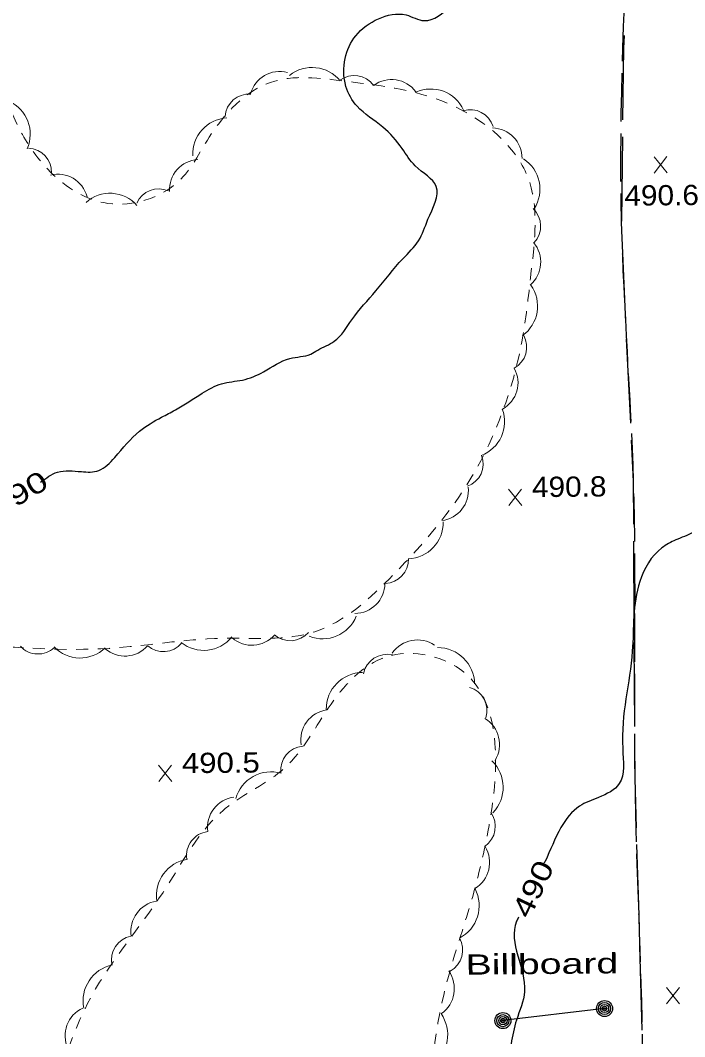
# Model space of a CAD drawing. Extents: x 2362213 to 2366494, y 6968794 to 6978110.
# Drawn here: x 2364075.5 to 2364233.1, y 6971102 to 6971343.1 of the extents above; entities that cross this region are included whole.
import ezdxf
from ezdxf.enums import TextEntityAlignment as Align

# ---------------------------------------------------------------- set-up
doc = ezdxf.new("R2010")
doc.units = 0
doc.header["$LTSCALE"] = 1.9
for name, pattern in [('DASH_DOUBLE_DOT', [9.2, 5, -1.2, 0.3, -1.2, 0.3, -1.2]), ('LONG_DASHED', [7.5, 6, -1.5]), ('SHORT_DASHED', [2.7, 1.5, -1.2])]:
    doc.linetypes.add(name, pattern=pattern)
for name, color, linetype, lineweight in [('21', 7, 'Continuous', 25), ('25', 7, 'Continuous', 25), ('29', 7, 'Continuous', 13), ('3', 7, 'Continuous', 25), ('31', 7, 'Continuous', 25)]:
    doc.layers.add(name, color=color, linetype=linetype, lineweight=lineweight)

msp = doc.modelspace()

# ---------------------------------------------------------------- linework, layer by layer
at = {"layer": '21'}
msp.add_line((2364214.103, 6971108.656), (2364189.99, 6971105.785), dxfattribs=at)
for centre, radius in [((2364214.103, 6971108.656), 1.9), ((2364214.103, 6971108.656), 1.442), ((2364214.103, 6971108.656), 0.973), ((2364189.989, 6971105.786), 1.9), ((2364189.989, 6971105.786), 1.442), ((2364214.103, 6971108.656), 0.539), ((2364214.103, 6971108.656), 0.192), ((2364189.989, 6971105.786), 0.973), ((2364189.989, 6971105.786), 0.539), ((2364189.989, 6971105.786), 0.192)]:
    msp.add_circle(centre, radius, dxfattribs=at)
at = {"layer": '25', "linetype": 'DASH_DOUBLE_DOT'}
msp.add_spline([(2363816.795, 6971226.248), (2363836.192, 6971228.743), (2363863.6, 6971232.244), (2363891.907, 6971241.034), (2363911.32, 6971252.379), (2363929.963, 6971264.788), (2363940.409, 6971286.278), (2363942.727, 6971325.332), (2363941.383, 6971367.741), (2363938.463, 6971413.955), (2363937.543, 6971444.378), (2363937.965, 6971480.914), (2363941.427, 6971504.899), (2363955.274, 6971529.442), (2363974.498, 6971547.954), (2363997.437, 6971571.335), (2364022.06, 6971595.32), (2364046.427, 6971617.784), (2364077.18, 6971641.847), (2364103.769, 6971659.921), (2364135.432, 6971677.483), (2364156.91, 6971686.249), (2364180.665, 6971699.435), (2364191.866, 6971712.133), (2364196.962, 6971724.112), (2364199.499, 6971738.027), (2364203.925, 6971746.789), (2364205.547, 6971755.055), (2364206.323, 6971765.933), (2364203.089, 6971775.782), (2364197.916, 6971788.864), (2364196.4, 6971794.69), (2364192.699, 6971817.855), (2364188.314, 6971835.234), (2364178.374, 6971856.091), (2364165.476, 6971870.579), (2364153.815, 6971875.758), (2364136.42, 6971874.132), (2364124.676, 6971865.15), (2364109.209, 6971855.172), (2364086.924, 6971843.049), (2364061.841, 6971828.48), (2364035.112, 6971814.726), (2364009.35, 6971806.269), (2363986.23, 6971807.199), (2363963.329, 6971808.291), (2363950.418, 6971808.328), (2363938.733, 6971812.987), (2363917.967, 6971814.529), (2363897.922, 6971820.129), (2363873.481, 6971822.206), (2363845.158, 6971820.416), (2363820.408, 6971817.11)], degree=3, dxfattribs=at)
at = {"layer": '29'}
for centre, radius, start, end in [((2364144.734, 6971323.335), 8.559, 38.83805, 128.83805), ((2364137.026, 6971323.811), 7.136, 74.94769, 164.94769), ((2364154.728, 6971324.267), 5.703, 36.35417, 126.35417), ((2364163.577, 6971321.901), 7.136, 36.35417, 126.35417), ((2364172.881, 6971318.227), 8.559, 24.51038, 114.51038), ((2364129.775, 6971319.879), 5.703, 86.05685, 176.05685), ((2364069.311, 6971316.099), 8.559, 335.85158, 65.85158), ((2364182.218, 6971316.189), 5.703, 17.31893, 107.31893), ((2364124.997, 6971311.391), 8.559, 93.18201, 183.18201), ((2364187.397, 6971310.406), 7.136, 359.05405, 89.05405), ((2364077.243, 6971307.022), 5.703, 358.04296, 88.04296), ((2364118.064, 6971302.935), 7.136, 93.60649, 183.60649), ((2364190.229, 6971303.04), 8.559, 326.99181, 56.99181), ((2364084.429, 6971299.451), 7.136, 14.45092, 104.45092), ((2364108.335, 6971297.394), 5.703, 66.03857, 156.03857), ((2364096.793, 6971293.498), 8.559, 41.65351, 131.65351), ((2364193.243, 6971294.273), 5.703, 316.72271, 46.72271), ((2364191.829, 6971285.712), 7.136, 310.43021, 40.43021), ((2364189.661, 6971275.27), 8.559, 305.58174, 35.58174), ((2364189.935, 6971265.567), 5.703, 298.88438, 28.88438), ((2364186.438, 6971257.101), 7.136, 298.88438, 28.88438), ((2364181.836, 6971247.864), 8.559, 290.50928, 20.50928), ((2364179.605, 6971237.878), 5.703, 290.50928, 20.50928), ((2364174.674, 6971231.511), 7.136, 276.68588, 6.68588), ((2364167.271, 6971223.912), 8.559, 271.5228, 1.5228), ((2364161.913, 6971215.195), 5.703, 271.5228, 1.5228), ((2364154.857, 6971209.524), 7.136, 270.03125, 0.03125), ((2364147.265, 6971204.918), 8.559, 247.96175, 337.96175), ((2364119.052, 6971202.186), 8.559, 231.13252, 321.13252), ((2364130.462, 6971201.961), 7.136, 228.57088, 318.57088), ((2364139.544, 6971201.602), 5.703, 229.45018, 319.45018), ((2364079.718, 6971198.458), 5.703, 222.84431, 312.84431), ((2364089.696, 6971200.364), 8.559, 223.89049, 313.89049), ((2364100.313, 6971199.401), 7.136, 229.06354, 319.06354), ((2364109.466, 6971199.039), 5.703, 229.06354, 319.06354), ((2364169.691, 6971188.84), 7.261, 55.53473, 145.53473), ((2364174.566, 6971185.559), 8.709, 0.57127, 90.57127), ((2364162.594, 6971186.897), 5.803, 78.23246, 168.23246), ((2364156.79, 6971179.68), 8.709, 90.51768, 180.51768), ((2364180.388, 6971179.299), 5.803, 343.09095, 73.09095), ((2364149.292, 6971172.326), 7.261, 98.69944, 188.69944), ((2364181.933, 6971171.263), 7.261, 328.8938, 58.8938), ((2364143.069, 6971165.126), 5.803, 95.36919, 185.36919), ((2364181.335, 6971161.135), 8.709, 316.10442, 46.10442), ((2364135.008, 6971156.106), 8.709, 74.29481, 164.29481), ((2364127.171, 6971151.628), 7.261, 97.66789, 187.66789), ((2364182.376, 6971151.865), 5.803, 305.22681, 35.22681), ((2364120.737, 6971144.885), 5.803, 97.66789, 187.66789), ((2364179.572, 6971143.324), 7.261, 301.19128, 31.19128), ((2364116.534, 6971135.477), 8.709, 99.09881, 189.09881), ((2364175.659, 6971133.083), 8.709, 297.38299, 27.38299), ((2364109.013, 6971126.981), 7.261, 99.16573, 189.16573), ((2364102.932, 6971120.165), 5.803, 101.63679, 191.63679), ((2364174.647, 6971122.592), 5.803, 299.04081, 29.04081), ((2364099.121, 6971110.476), 8.709, 101.63679, 191.63679), ((2364171.207, 6971113.374), 7.261, 305.28262, 35.28262), ((2364093.401, 6971102.198), 7.261, 114.94069, 204.94069), ((2364168.197, 6971102.427), 8.709, 305.28262, 35.28262)]:
    msp.add_arc(centre, radius, start, end, dxfattribs=at)
at = {"layer": '29', "linetype": 'SHORT_DASHED'}
for points in [[(2363958.345, 6971080.968), (2363959.367, 6971110.081), (2363966.704, 6971146.251), (2363967.545, 6971179.782), (2363973.617, 6971194.169), (2363980.608, 6971204.597), (2363992.99, 6971211.884), (2364007.089, 6971219.36), (2364019.09, 6971226.664), (2364030.679, 6971240.455), (2364033.28, 6971261.431), (2364034.592, 6971270.724), (2364024.724, 6971273.51), (2364009.32, 6971261.273), (2364001.556, 6971241.718), (2363989.711, 6971229.675), (2363976.764, 6971239.632), (2363966.187, 6971282.442), (2363960.611, 6971317.682), (2363957.015, 6971360.299), (2363951.144, 6971399.235), (2363954.105, 6971438.966), (2363953.8, 6971466.864), (2363965.552, 6971480.296), (2363969.451, 6971483.614), (2363981.267, 6971478.816), (2363995.13, 6971458.587), (2364011.28, 6971427.329), (2364026.695, 6971402.565), (2364035.553, 6971388.279), (2364056.122, 6971359.063), (2364066.736, 6971339.683), (2364075.666, 6971316.627), (2364082.627, 6971307.143), (2364096.308, 6971299.663), (2364113.089, 6971304.893), (2364120.32, 6971315.352), (2364134.837, 6971328.352), (2364152.746, 6971328.633), (2364178.554, 6971322.647), (2364195.863, 6971306.002), (2364196.653, 6971282.968), (2364194.457, 6971266.746), (2364182.659, 6971234.892), (2364164.119, 6971211.685), (2364145.359, 6971198.026), (2364123.243, 6971196.475), (2364096.643, 6971194.101), (2364063.774, 6971195.039), (2364044.219, 6971195.392), (2364030.532, 6971193.921), (2364011.079, 6971188.985), (2364014.728, 6971166.059), (2364035.634, 6971153.969), (2364047.98, 6971132.295), (2364049, 6971116.494), (2364048.801, 6971081.77)], [(2364081.216, 6971079.448), (2364092.468, 6971111.708), (2364109.376, 6971136.22), (2364124.128, 6971156.071), (2364138.325, 6971165.807), (2364149.223, 6971180.872), (2364163.563, 6971192.418), (2364179.715, 6971189.242), (2364185.553, 6971146.235), (2364182.014, 6971132.502), (2364176.596, 6971114.539), (2364171.403, 6971076.977)]]:
    msp.add_spline(points, degree=3, dxfattribs=at)
at = {"layer": '3'}
for p, q in [((2364218.344, 6971315.456), (2364218.085, 6971295.463)), ((2364218.233, 6971291.464), (2364219.093, 6971271.481)), ((2364220.978, 6971219.527), (2364221.058, 6971199.526)), ((2364221.077, 6971195.526), (2364221.197, 6971175.527)), ((2364222.382, 6971123.535), (2364222.913, 6971103.539))]:
    msp.add_line(p, q, dxfattribs=at)
for points in [[(2364218.726, 6971339.451), (2364218.614, 6971336.499), (2364218.396, 6971319.457)], [(2364219.261, 6971267.482), (2364219.39, 6971264.454), (2364220.232, 6971247.511)], [(2364220.43, 6971243.512), (2364220.913, 6971233.717), (2364220.96, 6971223.527)], [(2364221.225, 6971171.526), (2364221.274, 6971163.247), (2364221.606, 6971151.53)], [(2364221.714, 6971147.529), (2364222.194, 6971130.694), (2364222.274, 6971127.534)]]:
    msp.add_lwpolyline(points, dxfattribs=at)
at = {"layer": '3', "linetype": 'LONG_DASHED'}
for points in [[(2364118.66, 6971886.644), (2364146.069, 6971889.065), (2364166.764, 6971887.562), (2364186.296, 6971873.697), (2364199.958, 6971847.346), (2364208.677, 6971819.148), (2364213.594, 6971781.743), (2364216.696, 6971756.331), (2364213.572, 6971721.07), (2364204.328, 6971701.38), (2364187.309, 6971689.688), (2364157.907, 6971673.898), (2364123.868, 6971656.972), (2364086.611, 6971634.296), (2364053.513, 6971603.49), (2364022.777, 6971570.405), (2363993.526, 6971540.935), (2363970.504, 6971508.506), (2363957.635, 6971479.931), (2363955.676, 6971433.66), (2363959.995, 6971379.149), (2363959.942, 6971319.615), (2363959.436, 6971274.099), (2363951.928, 6971247.576), (2363935.08, 6971232.535), (2363908.327, 6971221.22), (2363873.337, 6971215.735), (2363839.434, 6971212.732), (2363816.703, 6971210.696)], [(2363960.382, 6971079.168), (2363964.442, 6971143.189), (2363970.68, 6971210.763), (2363973.344, 6971269.091), (2363972.013, 6971330.121), (2363969.296, 6971385.528), (2363968.14, 6971421.838), (2363968.507, 6971457.823), (2363977.172, 6971496.138), (2363993.264, 6971521.202), (2364013.212, 6971544.683), (2364048.194, 6971583.399), (2364088.874, 6971622.428), (2364113.817, 6971640.166), (2364142.371, 6971656.608), (2364177.647, 6971670.885), (2364207.453, 6971685.06), (2364223.873, 6971712.518), (2364225.534, 6971718.694), (2364228.857, 6971680.603), (2364228.271, 6971597.254), (2364226.815, 6971505.436), (2364223.493, 6971446.851), (2364220.131, 6971377.826), (2364218.077, 6971295.182), (2364220.913, 6971233.717), (2364221.274, 6971163.247), (2364223.054, 6971098.13), (2364223.096, 6971078.009)]]:
    msp.add_spline(points, degree=3, dxfattribs=at)
at = {"layer": '31', "lineweight": 13}
for p, q in [((2364228.946, 6971306.876), (2364225.83, 6971310.727)), ((2364225.867, 6971306.847), (2364228.909, 6971310.756)), ((2364194.466, 6971228.005), (2364191.349, 6971231.855)), ((2364191.386, 6971227.975), (2364194.429, 6971231.884)), ((2364111.435, 6971162.511), (2364108.319, 6971166.36)), ((2364108.356, 6971162.482), (2364111.398, 6971166.39)), ((2364231.914, 6971109.786), (2364228.796, 6971113.636)), ((2364228.833, 6971109.756), (2364231.877, 6971113.666))]:
    msp.add_line(p, q, dxfattribs=at)
at = {"layer": '31'}
for points in [[(2364209.382, 6971409.125), (2364212.403, 6971411.114), (2364213.397, 6971411.743), (2364214.866, 6971412.977), (2364216.994, 6971414.197), (2364219.581, 6971415.582), (2364222.494, 6971415.28), (2364227.458, 6971415.807), (2364230.644, 6971416.299), (2364234.918, 6971415.988), (2364237.473, 6971415.483), (2364240.727, 6971416.075), (2364242.546, 6971416.262), (2364243.299, 6971415.958), (2364245.194, 6971414.326), (2364246.649, 6971410.7), (2364246.773, 6971407.071), (2364246.814, 6971400.731), (2364246.443, 6971389.297), (2364246.343, 6971376.665), (2364246.274, 6971361.794), (2364246.76, 6971348.658), (2364246.365, 6971330.183), (2364245.7, 6971312.876), (2364245.212, 6971295.871), (2364244.911, 6971282.297), (2364244.836, 6971270.256), (2364244.457, 6971256.522), (2364243.605, 6971239.873), (2364242.882, 6971234.956), (2364242.316, 6971233.44), (2364240.864, 6971230.496), (2364238.316, 6971224.072), (2364235.109, 6971221.591), (2364231.005, 6971219.812), (2364227.712, 6971217.941), (2364222.439, 6971209.93), (2364220.687, 6971193.412), (2364218.406, 6971170.339), (2364217.606, 6971162.012), (2364212.697, 6971158.725), (2364208.175, 6971156.682), (2364203.764, 6971151.6), (2364199.99, 6971143.573), (2364199.794, 6971143.171)], [(2364080.338, 6971233.518), (2364084.356, 6971235.895), (2364089.994, 6971236.019), (2364094.112, 6971236.268), (2364097.902, 6971239.386), (2364103.814, 6971245.602), (2364109.043, 6971248.942), (2364112.296, 6971250.653), (2364118.688, 6971254.624), (2364123.258, 6971256.878), (2364128.19, 6971257.755), (2364133.231, 6971259.712), (2364139.46, 6971262.892), (2364144.402, 6971263.909), (2364146.073, 6971264.865), (2364150.003, 6971266.973), (2364154.175, 6971272.053), (2364159.859, 6971278.907), (2364166.268, 6971286.529), (2364169.997, 6971290.794), (2364172.219, 6971295.876), (2364174.175, 6971303.675), (2364169.218, 6971308.538), (2364166.109, 6971312.638), (2364161.509, 6971317.765), (2364155.403, 6971322.697), (2364152.768, 6971327.412), (2364152.564, 6971334.04), (2364155.113, 6971339.415), (2364160.494, 6971343.456), (2364167.007, 6971344.358), (2364171.31, 6971342.999), (2364177.595, 6971346.699), (2364181.073, 6971352.084), (2364183.247, 6971360.054), (2364185.476, 6971366.495), (2364187.246, 6971373.913), (2364189.801, 6971380.797), (2364191.247, 6971385.451), (2364194.571, 6971387.153), (2364195.284, 6971387.82), (2364198.322, 6971392.249), (2364199.635, 6971394.022), (2364202.919, 6971396.694), (2364205.63, 6971400.789), (2364207.899, 6971406.211), (2364209.382, 6971409.125)], [(2364193.706, 6971130.363), (2364193.225, 6971129.348), (2364195.124, 6971112.716), (2364193.228, 6971105.926), (2364191.932, 6971100.254), (2364190.977, 6971087.125), (2364190.824, 6971078.042)]]:
    msp.add_spline(points, degree=3, dxfattribs=at)

# ---------------------------------------------------------------- texts
at = {"layer": '21', "width": 1.45}
msp.add_text('Billboard', height=4.8, rotation=0.546, dxfattribs=at).set_placement((2364181.156, 6971116.673))
at = {"layer": '31'}
for s, width, p in [('490.6', 1.1, (2364218.83, 6971299.1)), ('490.8', 1.1, (2364196.907, 6971229.968)), ('490.5', 1.15, (2364113.876, 6971164.474))]:
    msp.add_text(s, height=4.8, rotation=0.546, dxfattribs=dict(at, width=width)).set_placement(p)
for rotation, width, p in [(30.791, 1.35, (2364076.445, 6971228.713)), (64.538, 1.3, (2364199.3, 6971136.014))]:
    msp.add_text(' 490 ', height=4.8, rotation=rotation, dxfattribs=dict(at, width=width)).set_placement(p, align=Align.CENTER)

doc.saveas('drawing.dxf')
